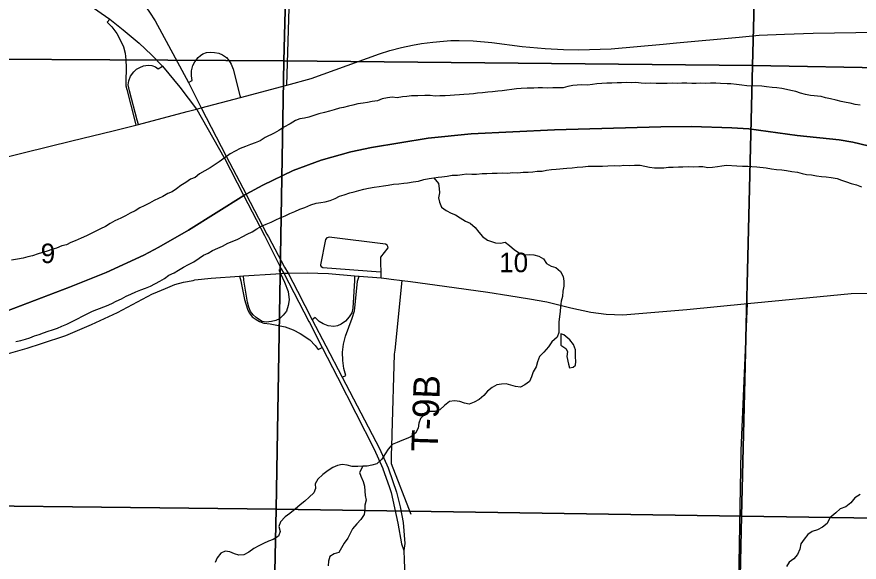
# Model space of a CAD drawing. Extents: x -6.2 to 37.4, y 0.2 to 22.2.
# Drawn here: x 4.132 to 5.038, y 17.311 to 17.898 of the extents above; entities that cross this region are included whole.
import ezdxf

# ---------------------------------------------------------------- set-up
doc = ezdxf.new("R2010")
doc.units = 0
for name, color, linetype in [('GM_X_County_Road', 7, 'Continuous'), ('GM_X_Interchange_Ramps', 7, 'Continuous'), ('GM_X_Major_River', 7, 'Continuous'), ('GM_X_Minor_Lake', 7, 'Continuous'), ('GM_X_Minor_River', 7, 'Continuous'), ('GM_X_Section', 7, 'Continuous'), ('GM_X_Section_Text', 7, 'Continuous'), ('GM_X_State_Route', 7, 'Continuous'), ('GM_X_Township', 7, 'Continuous'), ('GM_X_Township_Road', 7, 'Continuous'), ('GM_X_Township_Road_Text', 7, 'Continuous'), ('GM_X_US_Route', 7, 'Continuous')]:
    doc.layers.add(name, color=color, linetype=linetype)

msp = doc.modelspace()

# ---------------------------------------------------------------- linework, layer by layer
at = {"layer": 'GM_X_County_Road'}
for points in [[(4.82727, 17.86827), (4.84166, 17.86961), (4.90921, 17.87586), (4.93081, 17.87773), (4.95779, 17.87893), (4.98861, 17.88014), (5.05748, 17.88124), (5.08086, 17.88108)], [(4.10046, 17.74212), (4.13982, 17.75176), (4.1906, 17.76406), (4.23539, 17.77507), (4.25975, 17.78117), (4.26266, 17.78187), (4.31503, 17.79574), (4.32503, 17.79839), (4.32994, 17.79966), (4.37224, 17.81062), (4.4222, 17.82414), (4.44844, 17.83133), (4.48713, 17.84518), (4.52183, 17.85791), (4.53322, 17.8615), (4.54554, 17.8647), (4.5576, 17.8671), (4.56699, 17.8687), (4.57931, 17.87036), (4.5909, 17.87149), (4.59889, 17.87196), (4.60775, 17.87203), (4.62278, 17.87192), (4.64292, 17.87003), (4.67569, 17.8657), (4.70037, 17.86332), (4.71988, 17.86242), (4.73603, 17.86217), (4.7712, 17.86303), (4.82727, 17.86827)]]:
    msp.add_lwpolyline(points, dxfattribs=at)
at = {"layer": 'GM_X_Interchange_Ramps'}
for points in [[(4.23163, 17.89497), (4.22861, 17.89183), (4.23371, 17.88673), (4.23908, 17.87971), (4.24314, 17.87214), (4.24624, 17.86522), (4.24804, 17.85845), (4.24899, 17.85147), (4.24931, 17.843), (4.24888, 17.82777), (4.24899, 17.82322), (4.24994, 17.81952), (4.25866, 17.78583), (4.25975, 17.78117)], [(4.31616, 17.82684), (4.32019, 17.82893), (4.31955, 17.83411), (4.31955, 17.83951), (4.32082, 17.84512), (4.32304, 17.84924), (4.32685, 17.85369), (4.32929, 17.85591), (4.33176, 17.85773), (4.33581, 17.85909), (4.3405, 17.85952), (4.34432, 17.85919), (4.349, 17.85851), (4.35293, 17.85664), (4.35712, 17.85371), (4.36012, 17.85031), (4.36232, 17.84658), (4.36432, 17.84132), (4.37164, 17.81295), (4.37224, 17.81062)], [(4.26266, 17.78187), (4.26122, 17.78639), (4.25269, 17.81793), (4.25153, 17.82438), (4.25216, 17.82872), (4.25396, 17.83359), (4.25735, 17.83824), (4.26041, 17.84141), (4.2638, 17.84321), (4.26793, 17.8448), (4.27279, 17.84544), (4.27702, 17.84512), (4.28069, 17.84373), (4.2837, 17.84174), (4.28834, 17.84465)], [(4.41625, 17.62666), (4.41373, 17.62505), (4.41548, 17.62143), (4.41972, 17.61203), (4.42345, 17.6021), (4.42479, 17.5931), (4.42376, 17.58721), (4.42169, 17.58111), (4.41838, 17.57676), (4.41413, 17.57282), (4.41042, 17.57108), (4.40556, 17.56984), (4.39997, 17.56911), (4.39553, 17.56994), (4.39284, 17.5717), (4.38932, 17.57407), (4.38601, 17.57687), (4.38312, 17.58069), (4.38126, 17.58535), (4.37991, 17.59052), (4.37598, 17.6142), (4.37546, 17.61896)], [(4.37123, 17.61854), (4.37257, 17.61358), (4.3734, 17.60965), (4.37671, 17.59341), (4.37971, 17.58307), (4.38177, 17.57925), (4.38498, 17.57501), (4.38901, 17.5719), (4.39284, 17.56973), (4.39759, 17.56818), (4.40421, 17.56725), (4.41125, 17.56591), (4.42024, 17.56415), (4.42914, 17.56105), (4.43648, 17.55681), (4.44692, 17.54998), (4.45261, 17.54398), (4.45584, 17.53972), (4.46025, 17.54183)], [(4.49501, 17.61885), (4.49518, 17.61393), (4.49318, 17.58433), (4.49203, 17.57919), (4.48932, 17.57476), (4.48546, 17.57018), (4.48059, 17.56684), (4.4766, 17.56518), (4.47274, 17.56461), (4.46659, 17.56518), (4.4613, 17.56718), (4.45687, 17.5699), (4.45286, 17.57404), (4.44942, 17.5718)], [(4.48173, 17.50988), (4.48553, 17.51188), (4.4836, 17.51915), (4.48246, 17.52787), (4.48217, 17.53687), (4.48303, 17.54531), (4.48546, 17.55417), (4.49261, 17.57347), (4.49504, 17.58119), (4.49575, 17.58791), (4.49818, 17.61321), (4.49997, 17.61854)]]:
    msp.add_lwpolyline(points, dxfattribs=at)
at = {"layer": 'GM_X_Major_River'}
for points in [[(4.80353, 17.82626), (4.79805, 17.82675), (4.79294, 17.82666), (4.78783, 17.82677), (4.78253, 17.82668), (4.7776, 17.82659), (4.77192, 17.82614), (4.76662, 17.82606), (4.76113, 17.82598), (4.75581, 17.82533), (4.75107, 17.82466), (4.74595, 17.8242), (4.7397, 17.82432), (4.73478, 17.82404), (4.73004, 17.82357), (4.72453, 17.82273), (4.71958, 17.82131), (4.71427, 17.82104), (4.7086, 17.82115), (4.70329, 17.82088), (4.69757, 17.82111), (4.6927, 17.82109), (4.68796, 17.82081), (4.68077, 17.82077), (4.67452, 17.82051), (4.6694, 17.82024), (4.66433, 17.8194), (4.65915, 17.81874), (4.65403, 17.81808), (4.64928, 17.81761), (4.64359, 17.81696), (4.63847, 17.8165), (4.63297, 17.81585), (4.6275, 17.81537), (4.6233, 17.81472), (4.61837, 17.81444), (4.61264, 17.81388), (4.60794, 17.8137), (4.60283, 17.81342), (4.5979, 17.81295), (4.59278, 17.81249), (4.58691, 17.81242), (4.58199, 17.81233), (4.57632, 17.81282), (4.57067, 17.81287), (4.5632, 17.81273), (4.55644, 17.81246), (4.55132, 17.812), (4.54658, 17.81152), (4.54107, 17.8105), (4.5354, 17.81099), (4.53066, 17.81052), (4.52495, 17.80931), (4.5198, 17.80732), (4.51411, 17.80649), (4.50898, 17.80546), (4.50419, 17.80481), (4.49873, 17.80396), (4.4934, 17.80255), (4.48845, 17.80132), (4.48335, 17.80015), (4.47884, 17.79916), (4.47304, 17.79746), (4.46809, 17.79604), (4.46264, 17.79465), (4.45648, 17.79305), (4.45134, 17.79145), (4.446, 17.78947), (4.44106, 17.78862), (4.43631, 17.78796), (4.43136, 17.78616), (4.4256, 17.78229), (4.41909, 17.77882), (4.41372, 17.77533), (4.40855, 17.77259), (4.39899, 17.76785), (4.39361, 17.76435), (4.38808, 17.76219), (4.38312, 17.7602), (4.37778, 17.75822), (4.37205, 17.75587), (4.3665, 17.75295), (4.36133, 17.75002), (4.35576, 17.74615), (4.34922, 17.7417), (4.345, 17.73888), (4.33958, 17.73529), (4.33408, 17.73198), (4.32833, 17.72869), (4.32333, 17.7248), (4.31856, 17.72281), (4.31357, 17.7195), (4.3082, 17.71601), (4.30339, 17.7125), (4.29859, 17.70937), (4.2941, 17.70737), (4.28884, 17.70426), (4.27928, 17.6999), (4.2743, 17.69715), (4.26876, 17.69442), (4.26398, 17.69205)], [(5.03942, 17.80255), (5.03414, 17.80322), (5.02846, 17.80454), (5.02434, 17.80532), (5.01887, 17.80638), (5.0136, 17.80781), (5.00739, 17.80945), (5.00211, 17.81051), (4.99722, 17.81193), (4.98589, 17.81292), (4.98042, 17.81398), (4.97516, 17.8156), (4.97008, 17.81741), (4.96481, 17.81847), (4.9599, 17.81932), (4.95501, 17.82056), (4.94972, 17.82104), (4.94462, 17.82153), (4.93839, 17.82222), (4.93348, 17.82289), (4.9174, 17.82321), (4.91211, 17.82389), (4.90627, 17.82495), (4.90003, 17.82546), (4.89625, 17.82567), (4.88906, 17.82568), (4.88415, 17.82616), (4.87829, 17.82627), (4.87336, 17.82599), (4.86787, 17.8261), (4.86266, 17.82572), (4.85821, 17.82573), (4.85292, 17.82622), (4.84724, 17.82614), (4.84232, 17.82586), (4.83683, 17.82616), (4.83153, 17.82598), (4.82575, 17.82583), (4.81979, 17.82574), (4.81412, 17.82624), (4.80863, 17.82597), (4.80353, 17.82626)], [(4.60027, 17.72716), (4.60576, 17.72743), (4.61088, 17.72809), (4.61563, 17.72856), (4.6213, 17.72826), (4.62641, 17.72834), (4.63234, 17.72901), (4.6374, 17.72907), (4.64309, 17.72952), (4.64877, 17.72941), (4.65464, 17.72986), (4.65993, 17.72956), (4.66505, 17.73003), (4.67087, 17.72981), (4.67642, 17.73056), (4.68191, 17.73064), (4.68684, 17.73092), (4.69177, 17.73158), (4.69707, 17.73166), (4.70183, 17.7327), (4.70707, 17.73321), (4.71207, 17.73363), (4.72345, 17.73492), (4.72951, 17.73518), (4.73482, 17.73583), (4.7407, 17.73628), (4.74639, 17.73693), (4.7515, 17.73701), (4.76191, 17.7368), (4.7676, 17.73726), (4.77536, 17.73748), (4.78028, 17.73738), (4.78502, 17.73786), (4.7907, 17.73774), (4.79638, 17.73801), (4.80262, 17.73788), (4.80772, 17.73702), (4.81261, 17.73597), (4.81809, 17.73529), (4.823, 17.735), (4.82793, 17.73528), (4.83306, 17.73594), (4.83816, 17.73584), (4.8437, 17.7361), (4.8484, 17.73639), (4.85482, 17.73653), (4.86032, 17.73634), (4.86562, 17.73661), (4.8699, 17.7364), (4.87526, 17.73566), (4.88039, 17.73577), (4.88568, 17.73659), (4.89062, 17.73744), (4.89553, 17.73797), (4.90671, 17.7373), (4.91279, 17.73678), (4.91828, 17.73678), (4.92278, 17.73641), (4.92826, 17.7363), (4.93808, 17.73497), (4.94393, 17.73409), (4.94921, 17.73342), (4.95507, 17.73292), (4.96012, 17.73216), (4.96582, 17.73118), (4.97186, 17.73049), (4.97675, 17.72907), (4.98165, 17.72802), (4.98713, 17.72753), (4.99241, 17.72667), (4.99773, 17.72599), (5.0028, 17.72551), (5.00802, 17.72472), (5.01449, 17.72357), (5.01938, 17.72195), (5.02482, 17.71994), (5.02971, 17.71833), (5.03528, 17.71692), (5.0408, 17.71469)], [(4.13058, 17.54832), (4.1359, 17.54954), (4.14085, 17.55096), (4.14561, 17.55238), (4.15057, 17.55436), (4.15553, 17.55597), (4.1603, 17.55777), (4.16526, 17.55957), (4.17001, 17.5608), (4.17516, 17.56278), (4.18013, 17.56496), (4.18528, 17.56694), (4.19025, 17.56949), (4.19675, 17.57259), (4.2023, 17.57551), (4.20709, 17.57826), (4.21282, 17.5808), (4.2176, 17.58279), (4.2279, 17.58675), (4.23382, 17.58929), (4.2386, 17.59184), (4.24433, 17.59438), (4.24931, 17.59713), (4.25409, 17.59931), (4.25963, 17.60166), (4.26497, 17.60383), (4.26993, 17.60562), (4.27528, 17.60798), (4.28536, 17.6132), (4.2904, 17.61621), (4.2952, 17.61953), (4.30094, 17.62226), (4.30573, 17.62519), (4.31109, 17.62831), (4.31627, 17.63124), (4.322, 17.63416), (4.32776, 17.63802), (4.33256, 17.64115), (4.33734, 17.64352), (4.34231, 17.64608), (4.34786, 17.64862), (4.35282, 17.65079), (4.35857, 17.65409), (4.36334, 17.65608), (4.36944, 17.65824), (4.3748, 17.66116), (4.37959, 17.66391), (4.38495, 17.66646), (4.38993, 17.66958), (4.39491, 17.67233), (4.40006, 17.6745), (4.40541, 17.67685), (4.41019, 17.67922), (4.41516, 17.68121), (4.4205, 17.68357), (4.42529, 17.68613), (4.43063, 17.6881), (4.43616, 17.69074), (4.4417, 17.69243), (4.448, 17.69534), (4.45372, 17.69712), (4.45865, 17.69778), (4.46359, 17.69863), (4.46873, 17.69985), (4.47408, 17.70221), (4.47886, 17.70477), (4.48381, 17.70619), (4.48995, 17.70824), (4.49466, 17.70919), (4.49981, 17.71079), (4.50495, 17.71221), (4.51027, 17.71324), (4.51615, 17.71426), (4.52147, 17.71491), (4.52622, 17.71576), (4.53116, 17.71661), (4.53704, 17.71763), (4.54273, 17.71808), (4.54804, 17.71854), (4.55213, 17.71904), (4.55829, 17.72023), (4.5638, 17.72088), (4.56951, 17.72247), (4.5754, 17.72368), (4.58034, 17.72434), (4.58508, 17.725), (4.58911, 17.72561), (4.59476, 17.72633), (4.60027, 17.72716)], [(4.26398, 17.69205), (4.2588, 17.68893), (4.25364, 17.68638), (4.24866, 17.68345), (4.2435, 17.68109), (4.23719, 17.67799), (4.23202, 17.67544), (4.22703, 17.67194), (4.22158, 17.66945), (4.21651, 17.66684), (4.21154, 17.66448), (4.20638, 17.66211), (4.20084, 17.65957), (4.19427, 17.65676), (4.18976, 17.65467), (4.18499, 17.65249), (4.17985, 17.65108), (4.17431, 17.64873), (4.16936, 17.64712), (4.16421, 17.64533), (4.15434, 17.64258), (4.1484, 17.64053), (4.14326, 17.6393), (4.13851, 17.63807), (4.13242, 17.63687), (4.12578, 17.63587)]]:
    msp.add_lwpolyline(points, dxfattribs=at)
at = {"layer": 'GM_X_Minor_Lake'}
msp.add_line((4.71707, 17.55654), (4.71701, 17.5444), dxfattribs=at)
msp.add_lwpolyline([(4.71701, 17.5444), (4.71944, 17.54303), (4.72261, 17.54088), (4.72424, 17.53762), (4.72375, 17.53213), (4.72529, 17.52413), (4.72653, 17.52012), (4.73032, 17.52061), (4.73302, 17.52283), (4.73329, 17.52681), (4.73283, 17.53175), (4.73299, 17.53934), (4.73065, 17.54508), (4.72697, 17.55027), (4.72045, 17.55534), (4.71707, 17.55654)], dxfattribs=at)
at = {"layer": 'GM_X_Minor_River'}
for points in [[(4.58034, 17.72434), (4.58532, 17.71817), (4.58634, 17.71303), (4.58643, 17.70828), (4.58538, 17.70299), (4.5866, 17.69823), (4.58857, 17.69287), (4.59379, 17.68917), (4.59904, 17.6864), (4.60392, 17.6846), (4.60877, 17.68146), (4.61438, 17.67775), (4.61963, 17.67555), (4.62483, 17.6709), (4.6287, 17.66608), (4.63296, 17.66125), (4.63836, 17.65734), (4.64663, 17.65433), (4.65211, 17.65422), (4.65705, 17.65507), (4.6619, 17.65175), (4.6671, 17.6469), (4.67346, 17.64317), (4.67835, 17.64174), (4.68328, 17.64202), (4.68819, 17.64173), (4.69346, 17.64011), (4.69832, 17.63735), (4.70181, 17.63235), (4.70686, 17.6294), (4.71175, 17.62798), (4.71677, 17.6237), (4.7195, 17.61834), (4.72034, 17.61339), (4.72023, 17.60789), (4.71936, 17.60259), (4.71886, 17.59672), (4.71761, 17.59163), (4.71693, 17.58595), (4.71644, 17.58065), (4.71576, 17.57535), (4.71488, 17.5693), (4.71494, 17.56322), (4.71502, 17.5581), (4.71321, 17.55283), (4.70761, 17.54782), (4.70391, 17.54258), (4.69887, 17.53699), (4.69423, 17.53215), (4.69202, 17.52632), (4.69059, 17.52103), (4.68745, 17.51578), (4.68564, 17.51051), (4.68345, 17.50543), (4.67845, 17.50174), (4.67367, 17.49918), (4.66838, 17.49986), (4.6633, 17.50129), (4.65822, 17.50291), (4.65329, 17.50244), (4.64817, 17.50159), (4.64319, 17.49885), (4.63818, 17.49496), (4.6343, 17.49011), (4.62929, 17.48585), (4.62374, 17.48311), (4.6184, 17.48095), (4.61331, 17.482), (4.60824, 17.48381), (4.60257, 17.48449), (4.59726, 17.48365), (4.59187, 17.47958), (4.58704, 17.47475), (4.58133, 17.47316), (4.5764, 17.47288), (4.57144, 17.4707), (4.56603, 17.46569), (4.56441, 17.46041), (4.56373, 17.45511), (4.56078, 17.44986), (4.55559, 17.44579), (4.55081, 17.4438), (4.54604, 17.442), (4.54089, 17.43983), (4.53554, 17.43747), (4.53109, 17.43263), (4.52795, 17.42738), (4.52462, 17.42195), (4.51902, 17.41675), (4.51369, 17.41515), (4.50874, 17.41411), (4.50383, 17.4144), (4.49852, 17.41394), (4.49265, 17.41387), (4.487, 17.41531), (4.48191, 17.41599), (4.47659, 17.41495), (4.47181, 17.41278), (4.46664, 17.40966), (4.46105, 17.40522), (4.45547, 17.4004)], [(4.50383, 17.4144), (4.50049, 17.40753), (4.5019, 17.40344), (4.50443, 17.3977), (4.50584, 17.39274), (4.50629, 17.38741), (4.50657, 17.38267), (4.50741, 17.37753), (4.50617, 17.37243), (4.50626, 17.36769), (4.50558, 17.3622), (4.50168, 17.35697), (4.49742, 17.35212), (4.49295, 17.34671), (4.4902, 17.34183), (4.48782, 17.33676), (4.48393, 17.33153), (4.48117, 17.32627), (4.47823, 17.3214), (4.47328, 17.31998), (4.4683, 17.31705), (4.46706, 17.31214), (4.46657, 17.30703)], [(4.45547, 17.4004), (4.45271, 17.39533), (4.45317, 17.39039), (4.45137, 17.38549), (4.44636, 17.38104), (4.44153, 17.37659), (4.43671, 17.37251), (4.43113, 17.36788), (4.42555, 17.36344), (4.42055, 17.35975), (4.41552, 17.35435), (4.41371, 17.34946), (4.41511, 17.34412), (4.41311, 17.33904), (4.40755, 17.33554), (4.40241, 17.33375), (4.39724, 17.33101), (4.39208, 17.32865), (4.38672, 17.32572), (4.38134, 17.32166), (4.37597, 17.31873), (4.37067, 17.31865), (4.36578, 17.31989), (4.36091, 17.32227), (4.35581, 17.32275), (4.35104, 17.32076), (4.34714, 17.31553), (4.34496, 17.31064)], [(5.03918, 17.38369), (5.03362, 17.38001), (5.02934, 17.37479), (5.02376, 17.37054), (5.01785, 17.36819), (5.01303, 17.36411), (5.00667, 17.35855), (5.00371, 17.35273), (4.99889, 17.34865), (4.99335, 17.34592), (4.98782, 17.34394), (4.98302, 17.34062), (4.97912, 17.33558), (4.97561, 17.33053), (4.97436, 17.32486), (4.97197, 17.31941), (4.96809, 17.31455), (4.9629, 17.31105), (4.96015, 17.30618)]]:
    msp.add_lwpolyline(points, dxfattribs=at)
at = {"layer": 'GM_X_Section'}
for points in [[(3.93012, 18.35818), (4.4323, 18.35288), (4.41904, 17.85026), (3.91872, 17.85324)], [(4.4323, 18.35288), (4.9367, 18.34508), (4.92348, 17.84531), (4.41904, 17.85026)], [(4.41904, 17.85026), (4.41087, 17.36783), (3.90909, 17.37386), (3.91872, 17.85324)], [(4.92348, 17.84531), (4.91149, 17.36048), (4.41087, 17.36783), (4.41904, 17.85026)], [(3.90909, 17.37386), (4.41087, 17.36783), (4.40006, 16.86365), (3.89777, 16.87234)], [(4.41087, 17.36783), (4.91149, 17.36048), (4.90049, 16.85726), (4.40006, 16.86365)]]:
    msp.add_lwpolyline(points, close=True, dxfattribs=at)
for points in [[(5.08086, 17.84252), (4.92348, 17.84531), (4.9367, 18.34508), (5.08086, 18.34357)], [(5.08086, 17.35806), (4.91149, 17.36048), (4.92348, 17.84531), (5.08086, 17.84252)], [(5.08086, 16.85544), (4.90049, 16.85726), (4.91149, 17.36048), (5.08086, 17.35806)]]:
    msp.add_lwpolyline(points, dxfattribs=at)
at = {"layer": 'GM_X_State_Route'}
for points in [[(4.32121, 17.61413), (4.32314, 17.61451), (4.34062, 17.61637), (4.37123, 17.61854), (4.37546, 17.61896), (4.41048, 17.62112)], [(4.41048, 17.62112), (4.41548, 17.62143), (4.41891, 17.62179), (4.42352, 17.62184), (4.44403, 17.62206), (4.46698, 17.62133), (4.49501, 17.61885), (4.49997, 17.61854), (4.52386, 17.61668), (4.52952, 17.61603)], [(4.27867, 17.59991), (4.29164, 17.60551), (4.30163, 17.60965), (4.31104, 17.61213), (4.32121, 17.61413)], [(4.52952, 17.61603), (4.53461, 17.61544), (4.5465, 17.61399), (4.55529, 17.61296), (4.59185, 17.60782)], [(4.07189, 17.52499), (4.07693, 17.52578), (4.08592, 17.52754), (4.10453, 17.53147), (4.12253, 17.53561), (4.14249, 17.54119), (4.15821, 17.54605), (4.18437, 17.55494), (4.21208, 17.56663), (4.24, 17.57945), (4.27774, 17.59951), (4.27867, 17.59991)], [(4.59185, 17.60782), (4.63843, 17.60127), (4.66108, 17.59796), (4.68342, 17.59434), (4.70213, 17.59083), (4.72788, 17.58473), (4.74939, 17.58007), (4.76604, 17.57769), (4.78393, 17.57718), (4.8529, 17.58286), (4.91794, 17.58939)], [(4.91794, 17.58939), (4.95528, 17.5929), (4.98516, 17.59569), (5.02983, 17.59993), (5.0502, 17.60034), (5.06272, 17.59993), (5.08086, 17.59876)], [(4.89533, 16.61235), (4.89538, 16.61542), (4.89686, 16.69589), (4.89963, 16.85581), (4.90468, 17.05937), (4.90553, 17.10762), (4.91122, 17.43124), (4.91794, 17.58939)]]:
    msp.add_lwpolyline(points, dxfattribs=at)
at = {"layer": 'GM_X_Township'}
for points in [[(4.12025, 17.581), (4.18835, 17.60674), (4.22767, 17.62264), (4.26818, 17.64116), (4.28445, 17.64975), (4.31625, 17.66826), (4.37586, 17.70531), (4.37699, 17.70602), (4.37836, 17.70677), (4.39618, 17.71653), (4.42888, 17.73237), (4.45904, 17.7433), (4.49123, 17.75251), (4.51323, 17.75703), (4.57415, 17.76712), (4.62051, 17.77184), (4.71027, 17.776), (4.82465, 17.7792), (4.85763, 17.77954), (4.90129, 17.77823), (4.91967, 17.77717), (4.97171, 17.76999), (5.01668, 17.7652), (5.03138, 17.76276), (5.08086, 17.75075)], [(5.08086, 17.75075), (5.03138, 17.76276), (5.01668, 17.7652), (4.97171, 17.76999), (4.91967, 17.77717), (4.90129, 17.77823), (4.85763, 17.77954), (4.82465, 17.7792), (4.71027, 17.776), (4.62051, 17.77184), (4.57415, 17.76712), (4.51323, 17.75703), (4.49123, 17.75251), (4.45904, 17.7433), (4.42888, 17.73237), (4.39618, 17.71653), (4.37836, 17.70677), (4.37699, 17.70602), (4.37586, 17.70531), (4.31625, 17.66826), (4.28445, 17.64975), (4.26818, 17.64116), (4.22767, 17.62264), (4.18835, 17.60674), (4.12025, 17.581)]]:
    msp.add_lwpolyline(points, dxfattribs=at)
at = {"layer": 'GM_X_Township_Road'}
msp.add_line((4.53868, 17.53887), (4.5465, 17.61399), dxfattribs=at)
for points in [[(4.4222, 17.82414), (4.42487, 17.90689), (4.42493, 17.90945)], [(4.52386, 17.61668), (4.52355, 17.63912), (4.53125, 17.64905), (4.53105, 17.6506), (4.53022, 17.65194), (4.52826, 17.65307), (4.4678, 17.66047), (4.46656, 17.66016), (4.46542, 17.65975), (4.46388, 17.6581), (4.45832, 17.63096), (4.45832, 17.62993), (4.45904, 17.62889), (4.4608, 17.62776), (4.52292, 17.62319)], [(4.53556, 17.44872), (4.53826, 17.53486), (4.53868, 17.53887)], [(4.55595, 17.36236), (4.53472, 17.41675), (4.53484, 17.42567), (4.5355, 17.44672), (4.53556, 17.44872)]]:
    msp.add_lwpolyline(points, dxfattribs=at)
at = {"layer": 'GM_X_US_Route'}
msp.add_line((4.41625, 17.62666), (4.41866, 17.62223), dxfattribs=at)
for points in [[(4.16699, 17.96896), (4.17348, 17.96776), (4.18478, 17.96534), (4.19673, 17.96129), (4.20803, 17.9569), (4.21899, 17.95163), (4.22963, 17.9456), (4.24115, 17.93749), (4.25197, 17.92824), (4.25909, 17.92133), (4.26785, 17.91184), (4.27423, 17.90268), (4.28035, 17.89329), (4.31616, 17.82684)], [(4.16794, 17.93365), (4.19152, 17.92082), (4.20929, 17.91029), (4.23163, 17.89497), (4.24615, 17.88371), (4.26326, 17.86929), (4.27664, 17.85673), (4.28834, 17.84465)], [(4.28834, 17.84465), (4.30711, 17.82201), (4.32503, 17.79839), (4.32527, 17.79796)], [(4.31616, 17.82684), (4.32994, 17.79966), (4.35701, 17.74777), (4.37828, 17.70686), (4.37848, 17.70649), (4.40069, 17.66388)], [(4.32527, 17.79796), (4.35437, 17.74656), (4.3546, 17.74612)], [(4.3546, 17.74612), (4.37565, 17.70566), (4.37597, 17.70504), (4.39828, 17.66225)], [(4.40069, 17.66388), (4.4023, 17.6608), (4.41984, 17.62845), (4.42352, 17.62184), (4.43352, 17.60253)], [(4.39828, 17.66225), (4.39967, 17.6596), (4.41625, 17.62666)], [(4.41866, 17.62223), (4.41891, 17.62179), (4.44583, 17.57), (4.44652, 17.56866)], [(4.43352, 17.60253), (4.44942, 17.5718), (4.46415, 17.54377), (4.48173, 17.50988), (4.52208, 17.43309), (4.53119, 17.41237), (4.53153, 17.41143)], [(4.44652, 17.56866), (4.46025, 17.54183), (4.47687, 17.5098), (4.51637, 17.43253), (4.52548, 17.41181), (4.52565, 17.41133)], [(4.52565, 17.41133), (4.5323, 17.3925), (4.53466, 17.38581), (4.54178, 17.35297), (4.54565, 17.33059), (4.5483, 17.32354)], [(4.53153, 17.41143), (4.54036, 17.38637), (4.54409, 17.37052), (4.54749, 17.35353), (4.54914, 17.33104), (4.5483, 17.32354)], [(4.5483, 17.32354), (4.54856, 17.31363), (4.54879, 17.30471), (4.54456, 17.11041), (4.54453, 17.10869), (4.5391, 16.85924), (4.53228, 16.54568), (4.53337, 16.52248), (4.5344, 16.51687), (4.54646, 16.46245), (4.55208, 16.44906), (4.55987, 16.4361), (4.58494, 16.40976), (4.58926, 16.40587), (4.62226, 16.38029), (4.63031, 16.37565), (4.6318, 16.37522), (4.63938, 16.37306), (4.66155, 16.36783), (4.71662, 16.35703), (4.72609, 16.35695)]]:
    msp.add_lwpolyline(points, dxfattribs=at)

# ---------------------------------------------------------------- texts
at = {"layer": 'GM_X_Section_Text'}
for s, height, p in [('9', 0.02093, (4.15727, 17.6327)), ('10', 0.020928, (4.65081, 17.62291))]:
    msp.add_text(s, height=height, rotation=0.00001, dxfattribs=at).set_placement(p)
at = {"layer": 'GM_X_Township_Road_Text'}
msp.add_text('T-9B', height=0.028409, rotation=88.04623, dxfattribs=at).set_placement((4.58448, 17.42957))

doc.saveas('drawing.dxf')
